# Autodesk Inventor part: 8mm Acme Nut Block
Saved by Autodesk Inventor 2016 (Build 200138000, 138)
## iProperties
Created: 2016-03
Part Number: 8mm Acme Nut Block
Material: Generic
Document SubType Name: Modeling
Designer: bongo_000
Density: 1 g/cm^3
Appearance: Default
Author: bongo_000
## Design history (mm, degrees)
feature "CUT-EXTRUDE4"
body "Solid1"
